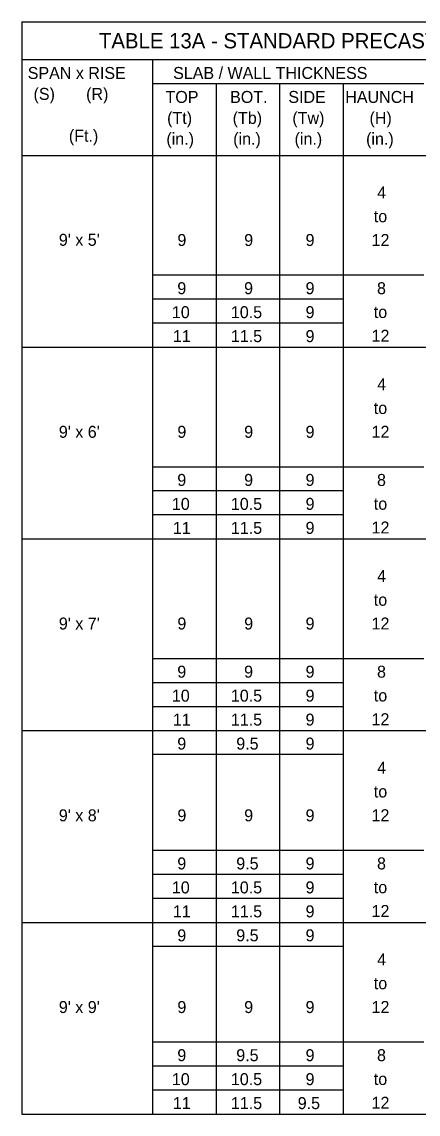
# Model space of a CAD drawing. Extents: x 10346.98 to 10349.19, y 76371.36 to 76372.62.
# Drawn here: x 10346.985 to 10347.193, y 76371.961 to 76372.535 of the extents above; entities that cross this region are included whole.
import ezdxf

# ---------------------------------------------------------------- set-up
doc = ezdxf.new("R2010")
doc.units = 0
doc.layers.add('AdhocPoint_dp', color=7, linetype='Continuous')
doc.layers.add('PlotBorder_dp', color=7, linetype='Continuous')

msp = doc.modelspace()

# ---------------------------------------------------------------- linework, layer by layer
at = {"layer": 'PlotBorder_dp'}
for p, q in [((10346.98451, 76372.53475), (10346.98451, 76371.96053)), ((10346.98451, 76372.53475), (10347.57925, 76372.53475)), ((10346.98451, 76372.51488), (10347.57925, 76372.51488)), ((10347.05314, 76372.51488), (10347.05314, 76371.96053)), ((10347.05314, 76372.50228), (10347.19559, 76372.50228)), ((10347.0865, 76372.50228), (10347.0865, 76371.96053)), ((10347.11986, 76372.50228), (10347.11986, 76371.96053)), ((10347.15323, 76372.50228), (10347.15323, 76371.96053)), ((10346.98451, 76372.46453), (10347.57925, 76372.46453)), ((10347.19559, 76372.40153), (10347.05314, 76372.40153)), ((10347.15323, 76372.38893), (10347.05314, 76372.38893)), ((10347.15323, 76372.37633), (10347.05314, 76372.37633)), ((10346.98451, 76372.36373), (10347.50186, 76372.36373)), ((10347.19559, 76372.30073), (10347.05314, 76372.30073)), ((10347.15323, 76372.28813), (10347.05314, 76372.28813)), ((10347.15323, 76372.27553), (10347.05314, 76372.27553)), ((10346.98451, 76372.26293), (10347.50186, 76372.26293)), ((10347.19559, 76372.19993), (10347.05314, 76372.19993)), ((10347.15323, 76372.18733), (10347.05314, 76372.18733)), ((10347.15323, 76372.17473), (10347.05314, 76372.17473)), ((10346.98451, 76372.16213), (10347.50186, 76372.16213)), ((10347.15323, 76372.14953), (10347.05314, 76372.14953)), ((10347.19559, 76372.09913), (10347.05314, 76372.09913)), ((10347.15323, 76372.08653), (10347.05314, 76372.08653)), ((10347.15323, 76372.07393), (10347.05314, 76372.07393)), ((10346.98451, 76372.06133), (10347.50186, 76372.06133)), ((10347.15323, 76372.04873), (10347.05314, 76372.04873)), ((10347.19559, 76371.99833), (10347.05314, 76371.99833)), ((10347.15323, 76371.98573), (10347.05314, 76371.98573)), ((10347.15323, 76371.97313), (10347.05314, 76371.97313)), ((10346.98451, 76371.96053), (10347.57925, 76371.96053))]:
    msp.add_line(p, q, dxfattribs=at)

# ---------------------------------------------------------------- texts
at = {"layer": 'AdhocPoint_dp'}
for s, height, p in [('TABLE 13A - STANDARD PRECAST BOX CULVERT DESIGNS (3" COVER) - 9\' SPANS', 0.008, (10347.02499, 76372.52081)), ('SLAB / WALL THICKNESS', 0.0063, (10347.06396, 76372.50472)), ('9', 0.0063, (10347.06616, 76372.39158)), ('9', 0.0063, (10347.10125, 76372.39158)), ('9', 0.0063, (10347.13354, 76372.39158)), ('10', 0.0063, (10347.06331, 76372.37898)), ('10.5', 0.0063, (10347.0943, 76372.37898)), ('9', 0.0063, (10347.13354, 76372.37898)), ('11', 0.0063, (10347.06383, 76372.36638)), ('11.5', 0.0063, (10347.0943, 76372.36638)), ('9', 0.0063, (10347.13354, 76372.36638)), ('9', 0.0063, (10347.06616, 76372.29078)), ('9', 0.0063, (10347.10125, 76372.29078)), ('9', 0.0063, (10347.13354, 76372.29078)), ('10', 0.0063, (10347.06331, 76372.27818)), ('10.5', 0.0063, (10347.0943, 76372.27818)), ('9', 0.0063, (10347.13354, 76372.27818)), ('11', 0.0063, (10347.06383, 76372.26558)), ('11.5', 0.0063, (10347.0943, 76372.26558)), ('9', 0.0063, (10347.13354, 76372.26558)), ('9', 0.0063, (10347.06616, 76372.18998)), ('9', 0.0063, (10347.10125, 76372.18998)), ('9', 0.0063, (10347.13354, 76372.18998)), ('10', 0.0063, (10347.06331, 76372.17738)), ('10.5', 0.0063, (10347.0943, 76372.17738)), ('9', 0.0063, (10347.13354, 76372.17738)), ('11', 0.0063, (10347.06383, 76372.16478)), ('11.5', 0.0063, (10347.0943, 76372.16478)), ('9', 0.0063, (10347.13354, 76372.16478)), ('9', 0.0063, (10347.06616, 76372.15218)), ('9.5', 0.0063, (10347.09713, 76372.15218)), ('9', 0.0063, (10347.13354, 76372.15218)), ('9', 0.0063, (10347.06616, 76372.08918)), ('9.5', 0.0063, (10347.09713, 76372.08918)), ('9', 0.0063, (10347.13354, 76372.08918)), ('10', 0.0063, (10347.06331, 76372.07658)), ('10.5', 0.0063, (10347.0943, 76372.07658)), ('9', 0.0063, (10347.13354, 76372.07658)), ('11', 0.0063, (10347.06383, 76372.06398)), ('11.5', 0.0063, (10347.0943, 76372.06398)), ('9', 0.0063, (10347.13354, 76372.06398)), ('9', 0.0063, (10347.06616, 76372.05138)), ('9.5', 0.0063, (10347.09713, 76372.05138)), ('9', 0.0063, (10347.13354, 76372.05138)), ('9', 0.0063, (10347.06616, 76371.98838)), ('9.5', 0.0063, (10347.09713, 76371.98838)), ('9', 0.0063, (10347.13354, 76371.98838)), ('10', 0.0063, (10347.06331, 76371.97578)), ('10.5', 0.0063, (10347.0943, 76371.97578)), ('9', 0.0063, (10347.13354, 76371.97578)), ('11', 0.0063, (10347.06383, 76371.96318)), ('11.5', 0.0063, (10347.0943, 76371.96318)), ('9.5', 0.0063, (10347.12942, 76371.96318))]:
    msp.add_text(s, height=height, dxfattribs=at).set_placement(p)
at = {"layer": 'PlotBorder_dp'}
for s, p in [('SPAN x RISE', (10346.98759, 76372.50472)), ('(S)       (R)', (10346.99064, 76372.49372)), ('TOP', (10347.05997, 76372.49212)), ('BOT.', (10347.0939, 76372.49212)), ('SIDE', (10347.12449, 76372.49212)), ('HAUNCH', (10347.15439, 76372.49212)), ('(Tt)', (10347.06081, 76372.48112)), ('(Tb)', (10347.09524, 76372.48112)), ('(Tw)', (10347.1266, 76372.48112)), ('(H)', (10347.16713, 76372.48112)), ('(Ft.)', (10347.00921, 76372.47172)), ('(in.)', (10347.06042, 76372.47012)), ('(in.)', (10347.09551, 76372.47012)), ('(in.)', (10347.12775, 76372.47012)), ('(in.)', (10347.16532, 76372.47012)), ('4', (10347.17117, 76372.44191)), ('to', (10347.16939, 76372.42941)), ("9' x 5'", (10347.00394, 76372.41701)), ('9', (10347.06621, 76372.41691)), ('9', (10347.1013, 76372.41691)), ('9', (10347.13354, 76372.41691)), ('12', (10347.16821, 76372.41691)), ('8', (10347.17106, 76372.39158)), ('to', (10347.16939, 76372.37908)), ('12', (10347.16821, 76372.36658)), ('4', (10347.17117, 76372.34111)), ('to', (10347.16939, 76372.32861)), ("9' x 6'", (10347.00394, 76372.31608)), ('9', (10347.06621, 76372.31608)), ('9', (10347.1013, 76372.31608)), ('9', (10347.13354, 76372.31608)), ('12', (10347.16821, 76372.31611)), ('8', (10347.17106, 76372.29078)), ('to', (10347.16939, 76372.27828)), ('12', (10347.16821, 76372.26578)), ('4', (10347.17117, 76372.24031)), ('to', (10347.16939, 76372.22781)), ("9' x 7'", (10347.00394, 76372.2153)), ('9', (10347.06621, 76372.2153)), ('9', (10347.1013, 76372.2153)), ('9', (10347.13354, 76372.2153)), ('12', (10347.16821, 76372.21531)), ('8', (10347.17106, 76372.18998)), ('to', (10347.16939, 76372.17748)), ('12', (10347.16821, 76372.16498)), ('4', (10347.17117, 76372.13951)), ('to', (10347.16939, 76372.12701)), ("9' x 8'", (10347.00394, 76372.11446)), ('9', (10347.06621, 76372.11446)), ('9', (10347.1013, 76372.11446)), ('9', (10347.13354, 76372.11446)), ('12', (10347.16821, 76372.11451)), ('8', (10347.17106, 76372.08918)), ('to', (10347.16939, 76372.07668)), ('12', (10347.16821, 76372.06418)), ('4', (10347.17117, 76372.03871)), ('to', (10347.16939, 76372.02621)), ("9' x 9'", (10347.00394, 76372.01368)), ('9', (10347.06621, 76372.01368)), ('9', (10347.1013, 76372.01368)), ('9', (10347.13354, 76372.01368)), ('12', (10347.16821, 76372.01371)), ('8', (10347.17106, 76371.98838)), ('to', (10347.16939, 76371.97588)), ('12', (10347.16821, 76371.96338))]:
    msp.add_text(s, height=0.0063, dxfattribs=at).set_placement(p)

doc.saveas('drawing.dxf')
